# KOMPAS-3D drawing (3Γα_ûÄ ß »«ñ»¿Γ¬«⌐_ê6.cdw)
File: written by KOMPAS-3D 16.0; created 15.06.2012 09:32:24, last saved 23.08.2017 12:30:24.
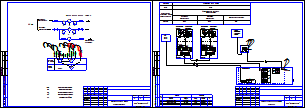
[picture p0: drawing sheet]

Sheets 1-2: A3, landscape

Title block, sheet 1: name: Руководство по эксплуатации; sheet number: 1; sheets: 27; organisation: ООО"Интелприбор"; sheet format: A3; stored path: W:\Users\smirnov_v\Desktop\шаблоны\4-х трубка\4-х трубка ГВС-max.cdw / D:\Проекты\Лыткарино\ул. Квартал 3А, д.25\710.74 РП.cdw; file name: 4-х трубка ГВС-max.cdw / 710.74 РП.cdw; cell 51: МО, Воскресенсикй р-н, п. Хорлово, ул. Интернациональная, д. 4; cell 320: Р
Title block, sheet 2: sheet number: 2

Views: Вид 2, Вид 3
Referenced files in C:\Program Files (x86)\ASCON\KOMPAS-3D V16\Sys\: spds.lcs, EngSys.lcs, GRAPHIC.LHS
Referenced files: graphic.tdp
Referenced files in W:\Users\smirnov_v\Desktop\шаблоны\4-х трубка\: 4-х трубка ГВС-max.cdw
Referenced files in D:\Проекты\Лыткарино\ул. Квартал 3А, д.25\: 710.74 РП.cdw
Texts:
  Смирнов В.С.
  УУ-3423
  GOST Common
  Normal
  List Paragraph
  heading 3
  для схемы
  txt
  Т0-элементы
  ВРУ
  Плата подключений
  СБ МКТС
  каб.
  Начало
  трассы
  Трассы
  Марка
  Проложен
  Изм. модуль (Т1)
  Изм. модуль (Т2)
  Изм. модуль (Т94)
  ВРУ 220В, 50 Гц
  ИМ (Т1)
  FTP
  ПВС
  Конец
  Кол-во и
  сеч. жил
  Длина,
  UP+
  UP-
  ИМП
  Лин
  Измерительный
  модуль М121
  Pt 100
  Преобразователь
  температуры
  давления
  приборы
  по месту
  Преобразователь расхода
  Термопреобразователь
  Преобразователь давления
  Преобразователь цифровой
  Системный блок МКТС
  шкаф
  учета
  UQIES
  Подающий
  трубопровод
  Обратный
  УУТЭ
  Функциональная схема
  Трубопровод
  подпитки
  Клемная колодка
  Счетчик
  расхода воды
  с импульсным
  выходом
  Агрегат
  Системный блок  МКТС
  Среда
  Вода
  параметра и место
  отбора импульса
  Учет тепловой энергии и
  теплоносителя
  Трубопровод подпитки
  ИМ1
  ИМ2
  ИМ3
  Размеры, параметризация
  сит. план
  подача ГВС
  обратка ГВС
  хвс
  обратка
  POLYLINE_STYLE_0.25_RGB_0_0_0
  стены
  Основная (не является границей для штриховки)
  POLYLINE_STYLE_0.18_RGB_0_0_0
  ХВС
  зеленая
  Красная тонкая
  арматура
  Подача
  Скрытая линия
  Ось Z
  Ось Y
  Ось X
  Образующая трубопровода (проектируемого)
  Трубопровод толщиной 0.6мм (одна линия)
  Трубопровод толщиной 1.2мм (одна линия)
  Трубопровод толщиной 1.0мм (одна линия)
  Трубопровод толщиной 0.8мм (одна линия)
  Трубопровод существующий (одна линия)
  Трубопровод невидимый (одна линия)
  Трубопровод демонтируемый (одна линия)
  Осевая трубопровода
  Осевая трубопровода (демонтируемого)
  Образующая трубопровода (существующего)
  Образующая трубопровода (невидимого)
  Изолированный трубопровод проектируемый (одна линия)
  Изолированный трубопровод существующий (одна линия)
  Образующая изоляции
  Изоляция
  Изолированный трубопровод невидимый (одна линия)
  Штрих пвс 075
  штрих пвс 2,5
  существующее оборудование
  Существующее оборудование
  K5LT_BASIC_RGB_0_0_255_THICK_0.53
  POLYLINE_STYLE_1.51_RGB_0_0_255
  POLYLINE_STYLE_0.50_RGB_128_128_128
  K5LT_AXLED_RGB_255_128_0_SC_1_THICK_0.18
  ACAD_ISO04W100_RGB_0_0_0_SC_1_THICK_0.18
  тонкая черная
  тонкая красная
  тонкая синяя
  тонкая оранж
  красн штрих
  пломбировка
  Провода
  синий штрих
  Стили документа
  G2co
  расход вторичной воды объемный
  расход вторичной воды объемный при 70гр
  Gco
  расход теплоносителя массовый
  расход теплоносит объемн подающ
  расход теплоносит объемн обр
  Лапир
  Ghvs
  Im1
  Im2
  Im3
  Im4
  Im5
  Khvs
  норматив ХВС
  число подъездов
  число этажей
  Nkv
  число квартир
  тепловая нагрузка на отопление
  сумма Q
  Qgvs
  тепловая нагрузка ГВС
  тепловая нагрузка на циркуляцию ГВС
  иммитовставка или под манометр
  ro1
  ro2
  ro3
  ro4
  верх предел темп граф
  нижн предел темп граф
  темп подачи ГВС
  темп обр ГВС
  темр хол воды
  vzdh
  Kchn
  Ktp
  Knp
  tnv
  Vклап
  KLP
  RPD
  RDS
  PUMP
  ro5
  beta
  tnv98
  Shifr
  Переход ГОСТ 17378-2001
  Переход
  ГОСТ
  Сталь 09Г2С ГОСТ 19281-89
  Втулка 20x50
  Лит-Масса-Масштаб
  Материал-Предприятие
  Title Specification
  Body Specification ( left align )
  Body Specificaton ( centered )
  Поз.
  Кол.
  Приме-
  чание
  Таблица спецификации
  Засыпка
  Штрих3
  Штрих2
  Штрих1
  Песок
  Штр0.5пр7
  Штр0.5пр12
  Штр0.3пр10
  Штр1.4пр21.21
  Штр1пр15
  Штр2.12пр35
  Штр1.5пр25
  Штр2.82пр42.42
  Штр2пр30
  SACNCR_ISO 1
  Электрощитовая
  Пр-1
  Ок-1
  Обозначение стандарта
  Типоразмер
  Пояснительная записка
  автоматизации
  Рабочие чертежи основного комплекта. ГОСТ Р 21.1101-2009 Ф3
  Стадия
  Лист
  Листов
  Изм.
  Кол.уч.
  №док.
  Подп.
  Дата
  Разраб.
  Пров.
  Т.контр.
  Н.контр.
  Утв.
  Изменение
  Номер документа
  Подпись
  Наименование объекта строительства, в состав которого входит здание, наим. микр
  Наименование здания (сооружения)
  Порядковый номер листа
  Количество листов в документе
  Наименование изображения
  Индекс предприятия, выпускающего документ
  Инв. № подл.
  Подп. и дата
  Взам. инв. №
  Инвентарный номер подлинника
  Подпись принявшего подлинник на хранение
  Инвентарный номер подлинника, взамен которого выпущен данный подлинник
  Согласовано
  Формат листа
  Согласование
  03 Рабочие чертежи основного комплекта. ГОСТ Р 21.1101-2009 Ф3
  Схема соединений внешних
  проводок
Dimensions and other numbers on the sheet: 220В; 50Гц; 1; 2; 3; 6; 5; 4; 2x2x0,52; 3х0,75; 20; 50; 4-20; 10; 1,2,3; 4,5; 6,7; 8,9; 7; 8; 9; 5,0; 3,2388; 0,0400; 40; 95; 3,1876; 70; 09Г2С; 27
